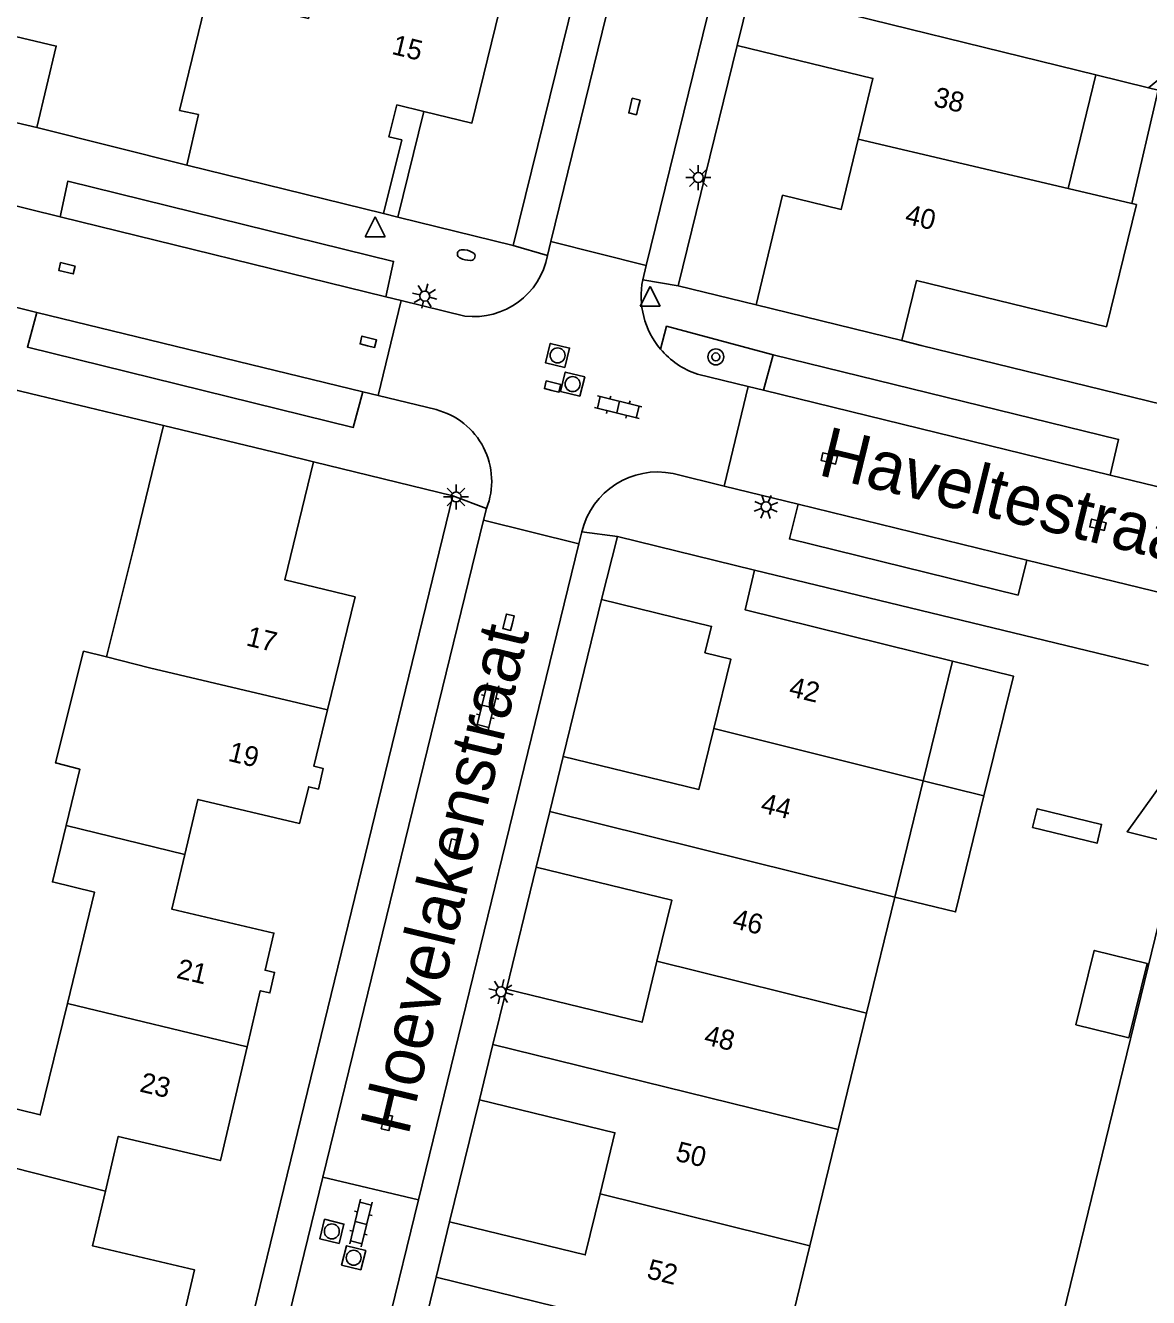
# Model space of a CAD drawing. Extents: x 128000 to 131008, y 398996 to 402500.
# Drawn here: x 128152.2 to 128208.5, y 399424.2 to 399488 of the extents above; entities that cross this region are included whole.
import ezdxf

# ---------------------------------------------------------------- set-up
doc = ezdxf.new("R2010")
doc.units = 0
for name, color, linetype in [('gg-afsc-erfafscheiding', 7, 'Continuous'), ('gg-afsc-muur', 7, 'Continuous'), ('gg-anno-huisnummerreeks BGT', 7, 'Continuous'), ('gg-anno-openbare ruimte label', 7, 'Continuous'), ('gg-bbg-bijgebouw', 7, 'Continuous'), ('gg-bbg-gedigitaliseerde bebouwing', 7, 'Continuous'), ('gg-bbg-hoofdgebouw', 7, 'Continuous'), ('gg-bbg-luifel en loopbrug', 7, 'Continuous'), ('gg-bbg-tussenscheiding', 7, 'Continuous'), ('gg-knt-verharding', 7, 'Continuous'), ('gg-knt-verharding nz', 7, 'Continuous'), ('gg-kntw-beschoeiing', 7, 'Continuous'), ('gt-grn-weggrens', 7, 'Continuous'), ('gt-symb-boom', 7, 'Continuous'), ('gt-symb-brandkraan', 7, 'Continuous'), ('gt-symb-klinker verharding', 7, 'Continuous'), ('gt-symb-kolk', 7, 'Continuous'), ('gt-symb-kolk center center', 7, 'Continuous'), ('gt-symb-lichtmast', 7, 'Continuous'), ('gt-symb-rioolschacht', 7, 'Continuous'), ('gt-symb-waterafsluiter', 7, 'Continuous')]:
    doc.layers.add(name, color=color, linetype=linetype)

# ---------------------------------------------------------------- blocks, each defined once
blk = doc.blocks.new('gt0-BR')
at = {"layer": 'gt-symb-brandkraan'}
for centre, radius, start, end in [((-0.244, 0), 0.206, 107.56694, 252.43307), ((0.599, -2.664), 3, 106.89205, 107.56694), ((0, -0.691), 0.938, 73.10799, 106.89205), ((-0.599, -2.664), 3, 72.43309, 73.10799), ((0.244, 0), 0.206, 287.56695, 72.43309), ((0.599, 2.664), 3, 252.43307, 253.10797), ((0, 0.691), 0.938, 253.10797, 286.89206), ((-0.599, 2.664), 3, 286.89206, 287.56695)]:
    blk.add_arc(centre, radius, start, end, dxfattribs=at)
blk = doc.blocks.new('gt0-KOLK')
at = {"layer": 'gt-symb-kolk'}
blk.add_lwpolyline([(0, 0), (0.375, 0), (0.375, 0.4), (-0.375, 0.4), (-0.375, 0), (0, 0)], dxfattribs=at)
blk = doc.blocks.new('gt0-WAFSL')
at = {"layer": 'gt-symb-waterafsluiter'}
for p, q in [((-0.5, -0.333), (0, 0.667)), ((0, 0.667), (0.5, -0.333)), ((0.5, -0.333), (-0.5, -0.333))]:
    blk.add_line(p, q, dxfattribs=at)
blk = doc.blocks.new('gt0-LMAST')
at = {"layer": 'gt-symb-lichtmast'}
for p, q in [((-0.182, 0.173), (-0.447, 0.438)), ((-0.005, 0.246), (-0.005, 0.621)), ((0.172, 0.173), (0.437, 0.438)), ((-0.255, -0.004), (-0.63, -0.004)), ((-0.182, -0.181), (-0.447, -0.446)), ((-0.005, -0.254), (-0.005, -0.629)), ((0.437, -0.446), (0.172, -0.181)), ((0.245, -0.004), (0.62, -0.004))]:
    blk.add_line(p, q, dxfattribs=at)
blk.add_circle((-0.005, -0.004), 0.25, dxfattribs=at)
blk = doc.blocks.new('gt0-KL1')
at = {"layer": 'gt-symb-klinker verharding'}
for p, q in [((-1.15, 0.3), (1.15, 0.3)), ((-1, -0.3), (-1, 0.3)), ((-0.5, 0.3), (-0.5, 0.45)), ((0, -0.3), (0, 0.3)), ((0.5, 0.3), (0.5, 0.45)), ((1, -0.3), (1, 0.3)), ((-1.15, -0.3), (1.15, -0.3)), ((-0.5, -0.45), (-0.5, -0.3)), ((0.5, -0.45), (0.5, -0.3))]:
    blk.add_line(p, q, dxfattribs=at)
blk = doc.blocks.new('gt0-RS')
at = {"layer": 'gt-symb-rioolschacht'}
blk.add_lwpolyline([(-0.5, -0.5), (0.5, -0.5), (0.5, 0.5), (-0.5, 0.5)], close=True, dxfattribs=at)
blk.add_circle((0, 0), 0.375, dxfattribs=at)
blk = doc.blocks.new('gt0-BOOM')
at = {"layer": 'gt-symb-boom'}
for radius in [0.4, 0.2]:
    blk.add_circle((0, 0), radius, dxfattribs=at)
blk = doc.blocks.new('gt0-KOLKCC')
at = {"layer": 'gt-symb-kolk center center'}
blk.add_lwpolyline([(-0.375, 0.2), (0.375, 0.2), (0.375, -0.2), (-0.375, -0.2)], close=True, dxfattribs=at)

msp = doc.modelspace()

# ---------------------------------------------------------------- linework, layer by layer
at = {"layer": 'gg-afsc-erfafscheiding'}
msp.add_line((128170.917, 399478.403), (128176.7, 399476.98), dxfattribs=at)
at = {"layer": 'gg-afsc-muur'}
for p, q in [((128152.827, 399482.894), (128160.336, 399481.012)), ((128196.18, 399472.21), (128197.151, 399471.972)), ((128159.171, 399467.948), (128147.117, 399470.851)), ((128166.694, 399466.131), (128173.676, 399464.432)), ((128188.8, 399460.7), (128208.548, 399455.928))]:
    msp.add_line(p, q, dxfattribs=at)
at = {"layer": 'gg-bbg-bijgebouw'}
msp.add_line((128152.827, 399482.894), (128150.079, 399483.529), dxfattribs=at)
msp.add_lwpolyline([(128151.053, 399487.623), (128153.797, 399486.97), (128152.827, 399482.894)], dxfattribs=at)
at = {"layer": 'gg-bbg-gedigitaliseerde bebouwing'}
for p, q in [((128204.512, 399479.829), (128205.901, 399485.527)), ((128208.541, 399484.877), (128205.901, 399485.527)), ((128207.704, 399479.08), (128204.512, 399479.829)), ((128159.171, 399467.948), (128157.7, 399461.9)), ((128157.7, 399461.9), (128156.308, 399456.354)), ((128154.286, 399447.905), (128154.975, 399450.735))]:
    msp.add_line(p, q, dxfattribs=at)
for points in [[(128207.325, 399491.386), (128209.776, 399490.788), (128210.29, 399489.943), (128209.188, 399485.422), (128208.541, 399484.877)], [(128159.97, 399483.75), (128161.399, 399489.587), (128166.436, 399488.357), (128167.088, 399491.028)], [(128206.44, 399472.895), (128207.937, 399479.025), (128207.704, 399479.08)], [(128156.308, 399456.354), (128155.163, 399456.641), (128153.757, 399451.041), (128154.975, 399450.735)], [(128154.355, 399438.982), (128155.714, 399444.563), (128153.598, 399445.078), (128154.286, 399447.905)], [(128150.861, 399433.916), (128152.995, 399433.396), (128154.355, 399438.982)]]:
    msp.add_lwpolyline(points, dxfattribs=at)
at = {"layer": 'gg-bbg-hoofdgebouw'}
for p, q in [((128187.931, 399487.01), (128188.607, 399489.786)), ((128172.218, 399483.702), (128170.858, 399484.036)), ((128170.203, 399478.579), (128160.336, 399481.012)), ((128196.92, 399475.22), (128196.18, 399472.21)), ((128196.92, 399475.22), (128206.44, 399472.895)), ((128196.18, 399472.21), (128188.87, 399474)), ((128165.129, 399466.513), (128159.171, 399467.948)), ((128166.694, 399466.131), (128165.129, 399466.513)), ((128181.93, 399462.39), (128181.121, 399459.23)), ((128188.8, 399460.7), (128181.93, 399462.39)), ((128167.388, 399453.697), (128168.77, 399459.36)), ((128198.72, 399456.15), (128197.252, 399450.138)), ((128178.533, 399448.606), (128179.21, 399451.37)), ((128197.252, 399450.138), (128195.831, 399444.32)), ((128177.85, 399445.82), (128178.533, 399448.606)), ((128195.831, 399444.32), (128194.408, 399438.492)), ((128175.682, 399436.934), (128176.36, 399439.7)), ((128194.408, 399438.492), (128192.987, 399432.674)), ((128175.001, 399434.16), (128175.682, 399436.934)), ((128192.987, 399432.674), (128191.561, 399426.836)), ((128172.836, 399425.273), (128173.51, 399428.04)), ((128191.561, 399426.836), (128190.14, 399421.018)), ((128172.16, 399422.5), (128172.836, 399425.273))]:
    msp.add_line(p, q, dxfattribs=at)
for points in [[(128176.016, 399488.775), (128174.63, 399483.11), (128172.218, 399483.702)], [(128193.991, 399482.301), (128194.73, 399485.35), (128187.931, 399487.01)], [(128159.97, 399483.75), (128160.921, 399483.538), (128160.336, 399481.012)], [(128170.203, 399478.579), (128171.113, 399482.269), (128170.462, 399482.429), (128170.858, 399484.036)], [(128188.87, 399474), (128190.2, 399479.5), (128193.14, 399478.79), (128193.991, 399482.301)], [(128168.77, 399459.36), (128165.253, 399460.218), (128166.694, 399466.131)], [(128188.8, 399460.7), (128188.33, 399458.71), (128198.72, 399456.15)], [(128186.751, 399452.759), (128187.6, 399456.25), (128186.31, 399456.56), (128186.64, 399457.88), (128181.121, 399459.23)], [(128160.239, 399446.455), (128160.89, 399449.21), (128165.99, 399448.01), (128166.45, 399449.85), (128166.93, 399449.73), (128167.18, 399450.76), (128166.7, 399450.88), (128167.388, 399453.697)], [(128179.21, 399451.37), (128186.01, 399449.71), (128186.751, 399452.759)], [(128163.359, 399436.806), (128164.02, 399439.62), (128164.5, 399439.51), (128164.74, 399440.54), (128164.26, 399440.65), (128164.7, 399442.51), (128159.591, 399443.71), (128160.239, 399446.455)], [(128183.905, 399441.099), (128184.65, 399444.16), (128177.85, 399445.82)], [(128176.36, 399439.7), (128183.16, 399438.04), (128183.905, 399441.099)], [(128156.254, 399429.57), (128156.9, 399432.32), (128162.02, 399431.11), (128163.359, 399436.806)], [(128181.054, 399429.438), (128181.8, 399432.5), (128175.001, 399434.16)], [(128159.389, 399419.939), (128160.05, 399422.76), (128160.53, 399422.65), (128160.77, 399423.67), (128160.29, 399423.78), (128160.73, 399425.63), (128155.61, 399426.83), (128156.254, 399429.57)], [(128173.51, 399428.04), (128180.31, 399426.38), (128181.054, 399429.438)]]:
    msp.add_lwpolyline(points, dxfattribs=at)
at = {"layer": 'gg-bbg-luifel en loopbrug'}
for p, q in [((128172.218, 399483.702), (128170.917, 399478.403)), ((128170.203, 399478.579), (128170.917, 399478.403)), ((128200.292, 399449.389), (128197.252, 399450.138))]:
    msp.add_line(p, q, dxfattribs=at)
for points in [[(128208.541, 399484.877), (128209.028, 399484.763), (128207.704, 399479.08)], [(128198.72, 399456.15), (128201.772, 399455.398), (128200.292, 399449.389)], [(128210.501, 399451.795), (128207.468, 399447.588), (128211.135, 399446.672), (128212.517, 399447.53)], [(128200.292, 399449.389), (128198.872, 399443.577), (128195.831, 399444.32)], [(128202.734, 399447.807), (128205.962, 399447.019), (128206.191, 399447.955), (128202.963, 399448.743), (128202.734, 399447.807)], [(128207.552, 399437.264), (128204.904, 399437.917), (128205.822, 399441.642), (128208.47, 399440.989), (128207.552, 399437.264)]]:
    msp.add_lwpolyline(points, dxfattribs=at)
at = {"layer": 'gg-bbg-tussenscheiding'}
for p, q in [((128188.607, 399489.786), (128205.901, 399485.527)), ((128193.991, 399482.301), (128204.512, 399479.829)), ((128158.472, 399455.811), (128156.308, 399456.354)), ((128158.472, 399455.811), (128167.388, 399453.697)), ((128186.751, 399452.759), (128197.252, 399450.138)), ((128178.533, 399448.606), (128195.831, 399444.32)), ((128154.286, 399447.905), (128160.239, 399446.455)), ((128183.905, 399441.099), (128194.408, 399438.492)), ((128154.355, 399438.982), (128163.359, 399436.806)), ((128175.682, 399436.934), (128192.987, 399432.674)), ((128150.183, 399431.131), (128156.254, 399429.57)), ((128181.054, 399429.438), (128191.561, 399426.836)), ((128172.836, 399425.273), (128190.14, 399421.018))]:
    msp.add_line(p, q, dxfattribs=at)
at = {"layer": 'gg-knt-verharding'}
for p, q in [((128194.5, 399549.39), (128176.7, 399476.98)), ((128178.59, 399477.177), (128188.573, 399518.02)), ((128183.37, 399475.983), (128193.385, 399516.842)), ((128187.931, 399487.01), (128184.96, 399474.95)), ((128153.986, 399478.413), (128144.389, 399480.766)), ((128178.42, 399476.48), (128178.59, 399477.177)), ((128178.59, 399477.177), (128183.37, 399475.983)), ((128183.37, 399475.983), (128183.19, 399475.25)), ((128152.814, 399473.625), (128145.18, 399475.485)), ((128184.96, 399474.95), (128188.87, 399474)), ((128169.924, 399469.458), (128171.076, 399474.222)), ((128170.306, 399474.411), (128171.076, 399474.222)), ((128171.076, 399474.222), (128174.272, 399473.439)), ((128189.729, 399471.499), (128189.247, 399469.719)), ((128197.151, 399471.972), (128211.541, 399468.44)), ((128185.929, 399470.53), (128188.475, 399469.908)), ((128169.924, 399469.458), (128169.163, 399469.643)), ((128187.265, 399464.92), (128188.475, 399469.908)), ((128188.475, 399469.908), (128189.247, 399469.719)), ((128172.831, 399468.75), (128169.924, 399469.458)), ((128187.265, 399464.92), (128184.712, 399465.545)), ((128234.686, 399458.61), (128206.623, 399465.471)), ((128151.55, 399373.82), (128173.676, 399464.432)), ((128190.981, 399464.011), (128187.265, 399464.92)), ((128175.214, 399463.202), (128175.36, 399463.8)), ((128167.158, 399430.275), (128175.214, 399463.202)), ((128175.214, 399463.202), (128179.994, 399462.03)), ((128180.141, 399462.631), (128179.994, 399462.03)), ((128179.994, 399462.03), (128171.949, 399429.144)), ((128202.441, 399461.207), (128232.003, 399453.973)), ((128181.121, 399459.23), (128179.21, 399451.37)), ((128177.85, 399445.82), (128176.36, 399439.7)), ((128175.001, 399434.16), (128173.51, 399428.04)), ((128165.472, 399423.384), (128167.158, 399430.275)), ((128171.949, 399429.144), (128167.158, 399430.275)), ((128171.949, 399429.144), (128170.255, 399422.22))]:
    msp.add_line(p, q, dxfattribs=at)
for points in [[(128170.306, 399474.411), (128170.704, 399476.176), (128154.369, 399480.197), (128153.986, 399478.413)], [(128169.163, 399469.643), (128168.68, 399467.857), (128152.349, 399471.875), (128152.814, 399473.625)], [(128189.729, 399471.499), (128184.383, 399472.929), (128184.082, 399471.784)], [(128206.623, 399465.471), (128207.043, 399467.256), (128189.729, 399471.499)], [(128202.441, 399461.207), (128202.007, 399459.455), (128190.545, 399462.266), (128190.981, 399464.011)]]:
    msp.add_lwpolyline(points, dxfattribs=at)
for centre, radius, start, end in [((128174.727, 399477.167), 3.756, 263.03552, 349.45659), ((128187.239, 399474.444), 4.129, 168.7471, 220.11748), ((128187.24, 399474.448), 4.131, 220.14991, 251.50188), ((128171.914, 399465.16), 3.705, 338.46219, 75.66362), ((128183.932, 399461.727), 3.897, 78.45215, 166.58265)]:
    msp.add_arc(centre, radius, start, end, dxfattribs=at)
at = {"layer": 'gg-knt-verharding nz'}
for p, q in [((128170.306, 399474.411), (128153.986, 399478.413)), ((128169.163, 399469.643), (128152.814, 399473.625)), ((128206.623, 399465.471), (128189.247, 399469.719)), ((128190.981, 399464.011), (128202.441, 399461.207))]:
    msp.add_line(p, q, dxfattribs=at)
at = {"layer": 'gg-kntw-beschoeiing'}
msp.add_lwpolyline([(128211.774, 399446.513), (128209.58, 399445.15), (128198.622, 399400.277)], dxfattribs=at)
at = {"layer": 'gt-grn-weggrens'}
for p, q in [((128178.42, 399476.48), (128176.7, 399476.98)), ((128183.19, 399475.25), (128184.96, 399474.95)), ((128175.36, 399463.8), (128173.676, 399464.432)), ((128181.93, 399462.39), (128180.141, 399462.631))]:
    msp.add_line(p, q, dxfattribs=at)

# ---------------------------------------------------------------- block references
at = {"layer": 'gt-symb-boom'}
msp.add_blockref('gt0-BOOM', (128186.854, 399471.395), dxfattribs=at)
at = {"layer": 'gt-symb-brandkraan', "rotation": -13.71646932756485}
msp.add_blockref('gt0-BR', (128174.341, 399476.497), dxfattribs=at)
at = {"layer": 'gt-symb-klinker verharding'}
for p, rotation in [((128181.961, 399468.875), -13.8834180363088), ((128175.419, 399453.866), 76.22785456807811), ((128169.066, 399427.981), 76.22785456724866)]:
    msp.add_blockref('gt0-KL1', p, dxfattribs=dict(at, rotation=rotation))
at = {"layer": 'gt-symb-kolk'}
for p, rotation in [((128182.965, 399483.895), 76.22785456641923), ((128169.387, 399471.955), -13.772145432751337), ((128178.626, 399469.712), -13.772145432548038), ((128192.495, 399466.114), -13.772145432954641), ((128205.961, 399462.785), -13.77214543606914), ((128176.657, 399458.046), 76.2835306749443), ((128173.911, 399446.776), 76.28353067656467), ((128170.559, 399432.977), 76.28353067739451)]:
    msp.add_blockref('gt0-KOLK', p, dxfattribs=dict(at, rotation=rotation))
at = {"layer": 'gt-symb-kolk center center', "rotation": -13.716469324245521}
msp.add_blockref('gt0-KOLKCC', (128154.329, 399475.836), dxfattribs=at)
at = {"layer": 'gt-symb-lichtmast'}
for p in [(128185.981, 399480.386), (128173.842, 399464.378)]:
    msp.add_blockref('gt0-LMAST', p, dxfattribs=at)
for p, rotation in [((128172.269, 399474.444), -13.772145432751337), ((128189.373, 399463.889), 20.06634962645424), ((128176.085, 399439.577), 76.28353067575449)]:
    msp.add_blockref('gt0-LMAST', p, dxfattribs=dict(at, rotation=rotation))
at = {"layer": 'gt-symb-rioolschacht'}
for p, rotation in [((128178.921, 399471.468), 76.22785456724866), ((128179.676, 399470.029), 76.22785456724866), ((128167.607, 399427.561), 76.22785456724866), ((128168.701, 399426.238), 76.22785456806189)]:
    msp.add_blockref('gt0-RS', p, dxfattribs=dict(at, rotation=rotation))
at = {"layer": 'gt-symb-waterafsluiter'}
for p in [(128169.778, 399477.739), (128183.557, 399474.262)]:
    msp.add_blockref('gt0-WAFSL', p, dxfattribs=at)

# ---------------------------------------------------------------- texts
at = {"layer": 'gg-anno-huisnummerreeks BGT'}
for s, rotation, p in [('15', 346.2, (128170.562, 399486.587)), ('38', 346.4, (128197.713, 399483.973)), ('40', 346.4, (128196.286, 399478.087)), ('17', 346.3, (128163.262, 399456.942)), ('42', 346.4, (128190.468, 399454.402)), ('19', 346.4, (128162.36, 399451.154)), ('44', 346.4, (128189.051, 399448.574)), ('46', 346.4, (128187.631, 399442.775)), ('21', 346.9, (128159.773, 399440.273)), ('48', 346.3, (128186.211, 399436.948)), ('23', 346.8, (128157.928, 399434.578)), ('50', 346.3, (128184.78, 399431.114)), ('52', 346.4, (128183.346, 399425.221))]:
    msp.add_text(s, height=1, rotation=rotation, dxfattribs=at).set_placement(p)
at = {"layer": 'gg-anno-openbare ruimte label'}
for s, rotation, p in [('Haveltestraat', 346.2, (128191.917, 399465.49)), ('Hoevelakenstraat', 76.5, (128171.432, 399432.311))]:
    msp.add_text(s, height=2.5, rotation=rotation, dxfattribs=at).set_placement(p)

doc.saveas('drawing.dxf')
